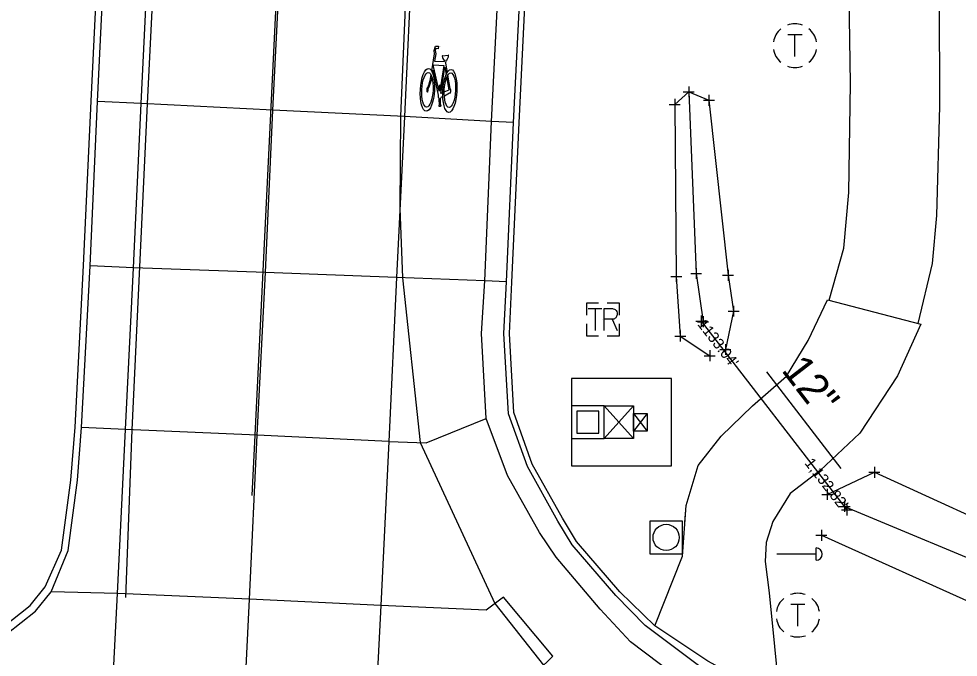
# Model space of a CAD drawing. Extents: x 207090 to 277928, y 600777 to 621109.
# Drawn here: x 261079.7 to 261165.7, y 612616.6 to 612675 of the extents above; entities that cross this region are included whole.
import ezdxf

# ---------------------------------------------------------------- set-up
doc = ezdxf.new("R2010")
doc.units = 0
for name, color, linetype in [('ATDIMS', 7, 'Continuous'), ('DR_X_Ditch', 7, 'Continuous'), ('DR_X_Storm_Sewer', 7, 'Continuous'), ('DR_X_Text', 7, 'Continuous'), ('PM_P_Edge_Line', 7, 'Continuous'), ('PM_P_Parking_Lot_Stall', 7, 'Continuous'), ('PM_P_Stop_Line', 7, 'Continuous'), ('PM_X_Cells', 7, 'Continuous'), ('PM_X_Edge_Line', 7, 'Continuous'), ('PM_X_Lane_Line', 7, 'Continuous'), ('PV_X_Curb', 7, 'Continuous'), ('PV_X_EOP', 7, 'Continuous'), ('PV_X_Joint', 7, 'Continuous'), ('PV_X_Walk', 7, 'Continuous'), ('SC_ProfileRun2', 7, 'Continuous'), ('SC_ProfileRun3', 7, 'Continuous'), ('SG_X_Controllers', 7, 'Continuous'), ('SG_X_Detection', 7, 'Continuous'), ('SG_X_Poles', 7, 'Continuous')]:
    doc.layers.add(name, color=color, linetype=linetype)

msp = doc.modelspace()

# ---------------------------------------------------------------- linework, layer by layer
at = {"layer": 'DR_X_Ditch'}
for points in [[(261141.01, 612668.348), (261141.697, 612651.72), (261142.322, 612647.308)], [(261155.273, 612630.412), (261170.785, 612623.936), (261181.737, 612622.038), (261224.753, 612617.764), (261254.852, 612619.275), (261313.097, 612621.284), (261371.065, 612622.869), (261453.806, 612606.883)]]:
    msp.add_lwpolyline(points, dxfattribs=at)
at = {"layer": 'DR_X_Storm_Sewer'}
msp.add_line((261142.161, 612647.367), (261155.494, 612630.086), dxfattribs=at)
at = {"layer": 'DR_X_Text'}
msp.add_line((261154.957, 612633.892), (261148.15, 612642.715), dxfattribs=at)
at = {"layer": 'PM_P_Edge_Line'}
for points in [[(261139.733, 612667.196), (261141.01, 612668.348), (261142.864, 612667.578), (261144.609, 612651.561), (261145.123, 612648.272), (261144.373, 612644.766)], [(261139.733, 612667.196), (261139.875, 612651.462), (261140.244, 612645.998), (261142.942, 612644.192)], [(261153.69, 612631.512), (261158.001, 612633.533), (261172.684, 612626.822), (261182.056, 612623.853), (261225.418, 612620.832), (261252.993, 612635.59), (261315, 612644.888), (261372.995, 612641.576)], [(261153.153, 612627.771), (261169.13, 612620.579), (261181.763, 612617.432), (261224.75, 612615.377), (261257.039, 612605.536), (261311.092, 612603.383), (261371.539, 612597.095), (261444.062, 612581.803), (261497.269, 612566.51), (261545.926, 612551.255), (261599.053, 612534.385), (261646.811, 612510.162), (261684.069, 612493.505), (261735.89, 612477.001), (261791.887, 612460.547), (261844.514, 612443.546), (261901.185, 612425.998), (261956.817, 612413.768), (262012.192, 612405.943), (262069.023, 612401.452), (262118.252, 612399.353), (262173.207, 612399.212), (262230.206, 612398.821)]]:
    msp.add_lwpolyline(points, dxfattribs=at)
at = {"layer": 'PM_P_Parking_Lot_Stall'}
msp.add_line((261133.168, 612647.518), (261133.168, 612647.518), dxfattribs=at)
for points in [[(261132.768, 612649.018), (261131.668, 612649.018), (261131.668, 612647.918)], [(261134.668, 612647.918), (261134.668, 612649.018), (261133.568, 612649.018)], [(261131.812, 612648.518), (261133.056, 612648.518)], [(261132.442, 612648.518), (261132.442, 612646.518)], [(261133.28, 612646.518), (261133.28, 612648.518), (261134.036, 612648.518), (261134.114, 612648.502), (261134.225, 612648.47), (261134.272, 612648.439), (261134.319, 612648.407), (261134.382, 612648.328), (261134.429, 612648.25), (261134.461, 612648.124), (261134.461, 612647.935), (261134.445, 612647.872), (261134.414, 612647.777), (261134.351, 612647.667), (261134.288, 612647.62), (261134.24, 612647.588), (261134.209, 612647.573), (261134.162, 612647.557), (261134.02, 612647.541), (261133.28, 612647.541)], [(261134.02, 612647.541), (261134.461, 612646.518)], [(261131.668, 612647.118), (261131.668, 612646.018), (261132.768, 612646.018)], [(261133.568, 612646.018), (261134.668, 612646.018), (261134.668, 612647.118)]]:
    msp.add_lwpolyline(points, dxfattribs=at)
at = {"layer": 'PM_P_Stop_Line'}
for p, q in [((261141.01, 612668.848), (261141.01, 612667.848)), ((261140.51, 612668.348), (261141.51, 612668.348)), ((261141.01, 612668.348), (261141.01, 612668.348)), ((261142.864, 612668.078), (261142.864, 612667.078)), ((261139.233, 612667.196), (261140.233, 612667.196)), ((261139.733, 612667.696), (261139.733, 612666.696)), ((261139.733, 612667.196), (261139.733, 612667.196)), ((261142.364, 612667.578), (261143.364, 612667.578)), ((261142.864, 612667.578), (261142.864, 612667.578)), ((261139.875, 612651.962), (261139.875, 612650.962)), ((261141.197, 612651.72), (261142.197, 612651.72)), ((261141.697, 612652.22), (261141.697, 612651.22)), ((261141.697, 612651.72), (261141.697, 612651.72)), ((261144.109, 612651.561), (261145.109, 612651.561)), ((261144.609, 612652.061), (261144.609, 612651.061)), ((261144.609, 612651.561), (261144.609, 612651.561)), ((261139.375, 612651.462), (261140.375, 612651.462)), ((261139.875, 612651.462), (261139.875, 612651.462)), ((261144.623, 612648.272), (261145.623, 612648.272)), ((261145.123, 612648.772), (261145.123, 612647.772)), ((261145.123, 612648.272), (261145.123, 612648.272)), ((261141.822, 612647.308), (261142.822, 612647.308)), ((261142.322, 612647.808), (261142.322, 612646.808)), ((261142.322, 612647.308), (261142.322, 612647.308)), ((261140.244, 612646.498), (261140.244, 612645.498)), ((261139.744, 612645.998), (261140.744, 612645.998)), ((261140.244, 612645.998), (261140.244, 612645.998)), ((261142.942, 612644.692), (261142.942, 612643.692)), ((261143.873, 612644.766), (261144.873, 612644.766)), ((261144.373, 612645.266), (261144.373, 612644.266)), ((261144.373, 612644.766), (261144.373, 612644.766)), ((261142.442, 612644.192), (261143.442, 612644.192)), ((261142.942, 612644.192), (261142.942, 612644.192)), ((261157.501, 612633.533), (261158.501, 612633.533)), ((261158.001, 612634.033), (261158.001, 612633.033)), ((261158.001, 612633.533), (261158.001, 612633.533)), ((261153.69, 612632.012), (261153.69, 612631.012)), ((261153.19, 612631.512), (261154.19, 612631.512)), ((261153.69, 612631.512), (261153.69, 612631.512)), ((261155.273, 612630.912), (261155.273, 612629.912)), ((261154.773, 612630.412), (261155.773, 612630.412)), ((261155.273, 612630.412), (261155.273, 612630.412)), ((261152.653, 612627.771), (261153.653, 612627.771)), ((261153.153, 612628.271), (261153.153, 612627.271)), ((261153.153, 612627.771), (261153.153, 612627.771))]:
    msp.add_line(p, q, dxfattribs=at)
at = {"layer": 'PM_X_Cells'}
for p, q in [((261117.893, 612672.305), (261117.829, 612672.124)), ((261118.338, 612672.507), (261118.338, 612672.507)), ((261117.873, 612671.812), (261117.761, 612671.153)), ((261117.829, 612672.124), (261117.873, 612671.812)), ((261118.494, 612671.651), (261118.999, 612671.697)), ((261117.675, 612670.649), (261117.702, 612670.806)), ((261118.176, 612668.419), (261117.675, 612670.649)), ((261117.761, 612671.153), (261118.658, 612671.107)), ((261118.604, 612670.761), (261118.233, 612668.408)), ((261118.323, 612668.202), (261118.701, 612670.599)), ((261118.658, 612671.107), (261118.679, 612671.237)), ((261118.701, 612670.599), (261118.825, 612669.943)), ((261118.799, 612671.22), (261118.758, 612670.96)), ((261118.758, 612670.96), (261118.917, 612670.12)), ((261117.512, 612669.696), (261117.454, 612669.356)), ((261117.621, 612670.335), (261117.578, 612670.082)), ((261118.136, 612668.046), (261117.621, 612670.335)), ((261119.094, 612668.528), (261118.877, 612669.673)), ((261119.198, 612668.643), (261118.967, 612669.858)), ((261118.169, 612668.923), (261118.162, 612668.784)), ((261118.162, 612668.784), (261118.195, 612668.783)), ((261118.283, 612668.917), (261118.169, 612668.923)), ((261118.195, 612668.783), (261118.176, 612668.419)), ((261118.233, 612668.408), (261118.252, 612668.78)), ((261118.252, 612668.78), (261118.276, 612668.779)), ((261118.276, 612668.779), (261118.283, 612668.917)), ((261118.135, 612667.828), (261118.136, 612668.046)), ((261118.513, 612667.918), (261118.321, 612667.817)), ((261118.511, 612668.282), (261118.323, 612668.202)), ((261118.648, 612668.34), (261119.094, 612668.528)), ((261118.656, 612667.992), (261119.137, 612668.242)), ((261118.172, 612666.993), (261118.179, 612667.138)), ((261118.314, 612667.007), (261118.172, 612666.993)), ((261118.179, 612667.138), (261118.212, 612667.141)), ((261118.212, 612667.141), (261118.198, 612667.653)), ((261118.264, 612667.666), (261118.278, 612667.147)), ((261118.278, 612667.147), (261118.322, 612667.151)), ((261118.322, 612667.151), (261118.314, 612667.007))]:
    msp.add_line(p, q, dxfattribs=at)
for points in [[(261117.499, 612670.256), (261117.765, 612671.813), (261117.72, 612672.135), (261117.86, 612672.531), (261118.113, 612672.518)], [(261118.113, 612672.518), (261118.102, 612672.294), (261117.893, 612672.305)], [(261117.702, 612670.806), (261118.604, 612670.761)], [(261117.349, 612669.374), (261117.437, 612669.891)]]:
    msp.add_lwpolyline(points, dxfattribs=at)
for centre, radius, start, end in [((261118.511, 612671.608), 0.0466, 111.12911, 179.5051), ((261118.881, 612671.601), 0.417, 178.97262, 240.92102), ((261118.558, 612671.636), 0.48, 300.03067, 4.20984), ((261119.001, 612671.658), 0.0392, 20.50857, 92.32343), ((261114.176, 612670.113), 3.257, 335.23767, 346.88251), ((261114.176, 612670.113), 3.364, 333.43857, 346.99131)]:
    msp.add_arc(centre, radius, start, end, dxfattribs=at)
for centre, major_axis, ratio in [((261117.106, 612668.531), (0.108, 1.964), 0.326796), ((261117.11, 612668.532), (0.08, 1.586), 0.323056), ((261119.16, 612668.427), (0.108, 1.964), 0.326796), ((261119.166, 612668.492), (0.08, 1.586), 0.323056)]:
    msp.add_ellipse(centre, major_axis=major_axis, ratio=ratio, dxfattribs=at)
for centre, major_axis, ratio, start_param, end_param in [((261117.116, 612668.535), (0.009, 0.217), 0.326817, 6.147003, 11.358914), ((261119.18, 612668.432), (-0.015, -0.212), 0.334676, 5.842318, 9.382693), ((261118.228, 612667.823), (0.01, 0.176), 0.529371, 1.570796, 2.917784), ((261118.228, 612667.823), (0.01, 0.176), 0.529371, 3.642407, 4.712389)]:
    msp.add_ellipse(centre, major_axis=major_axis, ratio=ratio, start_param=start_param, end_param=end_param, dxfattribs=at)
at = {"layer": 'PM_X_Edge_Line'}
for points in [[(261089.523, 612622.076), (261090.091, 612637.413), (261091.504, 612667.248), (261093.003, 612697.244), (261094.274, 612727.122), (261095.583, 612757.175), (261097.047, 612787.031), (261098.277, 612817.125), (261099.725, 612846.979)], [(261122.832, 612845.883), (261121.404, 612816.002), (261120.149, 612786.056), (261118.77, 612755.995), (261117.368, 612725.974), (261115.928, 612696.08), (261114.651, 612666.116), (261114.591, 612657.714), (261114.842, 612651.327), (261116.442, 612636.254), (261123.278, 612621.512), (261127.74, 612615.888), (261131.796, 612612.306), (261136.656, 612608.872)]]:
    msp.add_lwpolyline(points, dxfattribs=at)
at = {"layer": 'PM_X_Lane_Line'}
msp.add_lwpolyline([(261160.185, 613848.044), (261157.224, 613788.518), (261153.456, 613714.102), (261149.709, 613638.684), (261147.551, 613594.321), (261143.713, 613519.629), (261141.457, 613474.813), (261139.954, 613444.818), (261137.702, 613400.001), (261135.47, 613355.016), (261131.726, 613280.274), (261129.505, 613235.343), (261125.774, 613160.566), (261123.529, 613115.606), (261121.22, 613070.714), (261117.677, 612995.939), (261114.343, 612921.159), (261112.359, 612876.25), (261110.37, 612831.526), (261106.972, 612756.617), (261104.955, 612711.682), (261101.326, 612636.936), (261101.039, 612631.407)], dxfattribs=at)
at = {"layer": 'PV_X_Curb'}
for points in [[(261082.135, 612623.045), (261083.637, 612626.392), (261084.485, 612632.825), (261084.869, 612637.668), (261085.642, 612652.466), (261086.336, 612667.495), (261087.07, 612682.547), (261087.764, 612697.488), (261088.453, 612712.434), (261089.159, 612727.369), (261089.899, 612742.429), (261090.55, 612757.406), (261091.249, 612772.194), (261091.908, 612787.25), (261092.545, 612802.136), (261093.262, 612817.358), (261093.932, 612832.304), (261094.593, 612847.213), (261095.267, 612862.093), (261095.65, 612868.752), (261094.558, 612875.963)], [(261162.222, 612609.546), (261157.708, 612610.383), (261154.423, 612611.045), (261149.35, 612612.687), (261147.828, 612613.509), (261142.777, 612616.239), (261139.205, 612618.615), (261137.909, 612619.478), (261134.707, 612622.588), (261130.758, 612627.188), (261129.474, 612629.326), (261126.704, 612634.279), (261125.009, 612638.996), (261124.605, 612646.219), (261124.839, 612650.927), (261125.492, 612665.512), (261126.24, 612680.571)], [(261060.932, 612624.295), (261062.151, 612622.315), (261063.581, 612621.2), (261066.065, 612619.591), (261068.17, 612618.64), (261069.767, 612618.047), (261071.27, 612617.641), (261073.51, 612617.633), (261075.626, 612618.16), (261078.25, 612619.364), (261080.751, 612621.326), (261082.135, 612623.045)]]:
    msp.add_lwpolyline(points, dxfattribs=at)
at = {"layer": 'PV_X_EOP'}
for points in [[(261082.678, 612622.603), (261084.236, 612626.362), (261085.084, 612632.796), (261085.468, 612637.638), (261086.242, 612652.437), (261086.935, 612667.467), (261087.67, 612682.518), (261088.364, 612697.46), (261089.052, 612712.406), (261089.758, 612727.34), (261090.498, 612742.401), (261091.149, 612757.379), (261091.848, 612772.166), (261092.508, 612787.224), (261093.144, 612802.108), (261093.861, 612817.33), (261094.532, 612832.277), (261095.193, 612847.186), (261095.866, 612862.067), (261096.25, 612868.728), (261095.146, 612876.083)], [(261162.133, 612609.054), (261157.607, 612609.893), (261154.292, 612610.563), (261150.351, 612611.748), (261146.409, 612613.436), (261142.144, 612615.659), (261137.035, 612619.515), (261134.334, 612622.255), (261130.36, 612626.886), (261129.048, 612629.064), (261126.25, 612634.069), (261124.52, 612638.893), (261124.105, 612646.221), (261124.34, 612650.954), (261124.993, 612665.536), (261125.741, 612680.596)], [(261060.334, 612623.925), (261061.62, 612621.839), (261063.173, 612620.627), (261065.727, 612618.973), (261067.902, 612617.99), (261069.551, 612617.377), (261071.175, 612616.939), (261073.593, 612616.93), (261075.857, 612617.494), (261078.616, 612618.76), (261081.244, 612620.823), (261082.678, 612622.603)]]:
    msp.add_lwpolyline(points, dxfattribs=at)
at = {"layer": 'PV_X_Joint'}
for points in [[(261084.563, 612537.187), (261085.223, 612551.045), (261085.9, 612565.025), (261086.623, 612580.129), (261087.24, 612592.654), (261087.999, 612607.512), (261088.74, 612622.44), (261089.48, 612637.439), (261090.222, 612652.244), (261090.927, 612667.278), (261091.65, 612682.328), (261092.356, 612697.274), (261093.044, 612712.219), (261093.75, 612727.147), (261094.49, 612742.216), (261095.143, 612757.196), (261095.85, 612771.984), (261096.502, 612787.052), (261097.139, 612801.927), (261097.87, 612817.146), (261098.526, 612832.101), (261099.187, 612847.006)], [(261096.656, 612536.623), (261097.322, 612550.588), (261097.961, 612564.477), (261098.667, 612579.459), (261099.382, 612592.176), (261100.087, 612607.019), (261100.83, 612621.92), (261101.545, 612636.927), (261102.299, 612651.813), (261102.969, 612666.67), (261103.725, 612681.791), (261104.442, 612696.713), (261105.142, 612711.673), (261105.84, 612726.564), (261106.549, 612741.587), (261107.265, 612756.603), (261107.931, 612771.448), (261108.603, 612786.578), (261109.282, 612801.366), (261109.96, 612816.526), (261110.6, 612831.515), (261111.269, 612846.392)], [(261123.295, 612845.862), (261122.606, 612830.954), (261121.896, 612815.979), (261121.264, 612800.893), (261120.588, 612786.036), (261119.895, 612770.923), (261119.222, 612755.971), (261118.516, 612740.93), (261117.798, 612725.952), (261117.149, 612711.101), (261116.432, 612696.052), (261115.707, 612681.201), (261115.013, 612666.099), (261114.27, 612651.347), (261113.57, 612636.358), (261112.838, 612621.333), (261112.099, 612606.453), (261111.389, 612591.636), (261110.733, 612578.912), (261110.029, 612563.934), (261109.316, 612550.044), (261108.642, 612536.117)], [(261122.05, 612646.227), (261122.346, 612651.058), (261122.984, 612665.63), (261123.733, 612680.697), (261124.489, 612695.628), (261124.59, 612710.811), (261124.685, 612725.629), (261124.813, 612740.616), (261125.001, 612755.723), (261124.987, 612770.732), (261125.025, 612785.921), (261125.351, 612800.665), (261125.883, 612815.788), (261126.511, 612830.752), (261127.196, 612845.723)], [(261124.993, 612665.536), (261122.984, 612665.63), (261115.013, 612666.099), (261102.969, 612666.67), (261090.927, 612667.278), (261086.935, 612667.467)], [(261124.34, 612650.954), (261122.346, 612651.058), (261114.27, 612651.347), (261102.299, 612651.813), (261090.222, 612652.244), (261086.242, 612652.437)], [(261161.755, 612606.978), (261157.178, 612607.81), (261153.758, 612608.599), (261149.664, 612609.885), (261145.56, 612611.63), (261141.068, 612613.955), (261135.694, 612618.027), (261132.917, 612620.991), (261128.873, 612625.76), (261127.348, 612628.018), (261124.439, 612633.23), (261122.476, 612638.464), (261122.05, 612646.227)], [(261113.57, 612636.358), (261116.986, 612636.234), (261122.476, 612638.464)], [(261113.57, 612636.358), (261101.545, 612636.927), (261089.48, 612637.439), (261085.468, 612637.638)], [(261122.493, 612620.904), (261112.838, 612621.333), (261100.83, 612621.92), (261088.74, 612622.44), (261082.678, 612622.603)], [(261112.583, 612535.945), (261113.257, 612549.845), (261114.114, 612564.244), (261119.686, 612564.89), (261125.029, 612565.014), (261125.586, 612578.465), (261126.101, 612590.883), (261126.712, 612605.352), (261127.19, 612615.346), (261128.585, 612616.719), (261124.059, 612622.117), (261122.493, 612620.904)]]:
    msp.add_lwpolyline(points, dxfattribs=at)
at = {"layer": 'PV_X_Walk'}
for points in [[(261153.853, 612649.274), (261155.198, 612654.043), (261155.669, 612659.127), (261155.8, 612669.123), (261155.654, 612679.119), (261155.178, 612689.108), (261154.586, 612699.09), (261153.796, 612709.059), (261153.577, 612719.049), (261153.633, 612729.049), (261153.629, 612739.049), (261153.624, 612749.05), (261153.524, 612759.05), (261153.395, 612769.049), (261153.266, 612779.049), (261153.183, 612789.049), (261153.141, 612799.049), (261153.099, 612809.049), (261153.022, 612819.049), (261152.918, 612829.049)], [(261162.013, 612647.143), (261163.302, 612652.622), (261163.711, 612657.041), (261163.987, 612667.031), (261163.963, 612677.029), (261163.487, 612687.018), (261162.977, 612697.005), (261162.187, 612706.974), (261161.762, 612716.957), (261161.835, 612726.957), (261161.83, 612736.957), (261161.825, 612746.957), (261161.752, 612756.957), (261161.623, 612766.957), (261161.494, 612776.957), (261161.392, 612786.956), (261161.35, 612796.957), (261161.309, 612806.957), (261161.244, 612816.957), (261161.121, 612828.791)], [(261140.668, 612628.946), (261140.786, 612630.498), (261141.863, 612634.155), (261143.983, 612636.844), (261146.862, 612639.625), (261149.956, 612642.331), (261151.955, 612645.587), (261153.705, 612649.313), (261162.255, 612647.08), (261160.124, 612642.354), (261156.679, 612637.106), (261153.045, 612633.695), (261150.29, 612631.589), (261148.698, 612629.032), (261148.112, 612627.118), (261148.011, 612625.357), (261148.386, 612622.494), (261149.35, 612612.687), (261147.828, 612613.509), (261142.777, 612616.239), (261139.205, 612618.615)], [(261139.205, 612618.615), (261137.909, 612619.478), (261140.432, 612625.841), (261140.786, 612630.498)]]:
    msp.add_lwpolyline(points, dxfattribs=at)
at = {"layer": 'SC_ProfileRun2'}
for p, q in [((261141.661, 612647.367), (261142.661, 612647.367)), ((261142.161, 612647.867), (261142.161, 612646.867)), ((261142.161, 612647.367), (261142.161, 612647.367)), ((261154.994, 612630.086), (261155.994, 612630.086)), ((261155.494, 612630.586), (261155.494, 612629.586)), ((261155.494, 612630.086), (261155.494, 612630.086))]:
    msp.add_line(p, q, dxfattribs=at)
at = {"layer": 'SC_ProfileRun3'}
for p, q in [((261150.08, 612673.58), (261151.38, 612673.58)), ((261150.73, 612671.58), (261150.73, 612673.58)), ((261150.73, 612672.58), (261150.73, 612672.58)), ((261150.35, 612621.459), (261151.65, 612621.459)), ((261151, 612619.459), (261151, 612621.459)), ((261151, 612620.459), (261151, 612620.459))]:
    msp.add_line(p, q, dxfattribs=at)
for centre, start, end in [((261150.729, 612672.579), 130.0806, 170.07213), ((261150.729, 612672.579), 70.05767, 110.10608), ((261150.729, 612672.579), 10.01689, 50.03919), ((261150.729, 612672.579), 190.01689, 230.03919), ((261150.729, 612672.579), 310.01144, 350.02638), ((261150.729, 612672.579), 250.05767, 290.04731), ((261151, 612620.459), 70.05767, 110.10608), ((261151, 612620.459), 130.0806, 170.07213), ((261151, 612620.459), 10.01689, 50.03919), ((261151, 612620.459), 190.01689, 230.03919), ((261151, 612620.459), 310.01144, 350.02638), ((261151, 612620.459), 250.05767, 290.04731)]:
    msp.add_arc(centre, 2, start, end, dxfattribs=at)
at = {"layer": 'SG_X_Controllers'}
for p, q in [((261133.289, 612639.611), (261135.954, 612636.611)), ((261135.954, 612639.611), (261133.289, 612636.611)), ((261135.954, 612638.92), (261137.2, 612637.302)), ((261137.2, 612638.92), (261135.954, 612637.302))]:
    msp.add_line(p, q, dxfattribs=at)
for points in [[(261130.289, 612642.109), (261130.289, 612634.112), (261139.45, 612634.112), (261139.45, 612642.109)], [(261130.289, 612639.611), (261130.289, 612636.611), (261133.289, 612636.611), (261133.289, 612639.611)], [(261133.289, 612639.611), (261135.954, 612639.611), (261135.954, 612636.611), (261133.289, 612636.611)], [(261130.79, 612639.11), (261130.79, 612637.111), (261132.789, 612637.111), (261132.789, 612639.11)], [(261135.954, 612638.92), (261137.2, 612638.92), (261137.2, 612637.302), (261135.954, 612637.302)]]:
    msp.add_lwpolyline(points, close=True, dxfattribs=at)
at = {"layer": 'SG_X_Detection'}
for p, q in [((261152.673, 612625.484), (261152.673, 612626.604)), ((261152.673, 612626.044), (261149.073, 612626.044))]:
    msp.add_line(p, q, dxfattribs=at)
msp.add_arc((261152.673, 612626.044), 0.56, 270.00019, 89.99981, dxfattribs=at)
at = {"layer": 'SG_X_Poles'}
msp.add_lwpolyline([(261137.448, 612626.069), (261140.448, 612626.069), (261140.448, 612629.069), (261137.448, 612629.069)], close=True, dxfattribs=at)
msp.add_circle((261138.948, 612627.569), 1.2, dxfattribs=at)

# ---------------------------------------------------------------- texts
at = {"layer": 'ATDIMS'}
for s, p in [("1133.04'", (261141.765, 612647.061)), ("1,132.82'", (261151.567, 612634.358))]:
    msp.add_text(s, height=1, rotation=307.65341, dxfattribs=at).set_placement(p)
at = {"layer": 'DR_X_Text'}
msp.add_text('12" ', height=2.8, rotation=307.65341, dxfattribs=at).set_placement((261149.424, 612642.867))

doc.saveas('drawing.dxf')
